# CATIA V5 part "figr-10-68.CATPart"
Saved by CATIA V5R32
Part number: Part1
Bounding box of the stored display mesh (mm): x -80.563 to 63.541, y -72 to 69, z -55 to 6.847
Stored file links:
  D:\PROJECTS\Project 2022\CATIA V5 6R 2022\Resources\Part Files\c10_catia_v5_6r2022_prt\c10_catia_v5_6r2022_prt\figr-10-68.CATPart
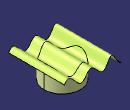
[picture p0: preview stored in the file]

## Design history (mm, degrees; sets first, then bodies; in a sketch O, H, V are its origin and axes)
Set1
  Sketch1 on xy-plane, origin (0, 0, 0), H (-1, 0, 0), V (0, -1, 0)
    circle A1 centre (0, 0) radius 45.985
  Extrude1: Element1 Sketch1, Lim1 56, Lim2 55, Direction xy-plane
  Sketch2 on zx-plane, origin (0, 0, 0), H (1, 0, 0), V (0, 0, -1)
    spline S1 through (-80.5635, 24.8913) (-73.6025, 19.8803) (-54.8525, -3.3629) (-35.1982, 19.8803) (-2.6271, -1.6506) (16.6996, 17.2854) (52.4104, -6.7877) (63.5409, 1.5862)
  Extrude2: Element1 Sketch2, Lim1 72, Lim2 69, Direction Sketch1.V
  Split1: ToCut Extrude1, Cutting Extrude2
Body1 (main body)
